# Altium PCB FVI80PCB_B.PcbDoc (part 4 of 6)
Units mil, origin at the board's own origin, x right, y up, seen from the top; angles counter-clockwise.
Board outline 3540 x 3115 mil, 12 copper layers (Top Layer, Int1(GND), Int2(Signal), Int3(GND), Int4(Signal), Int5 (GND&PW), Int6 (GND&PW), Int7(Signal), Int8(GND), Int9(Signal), Int10(GND), Bottom Layer), stack 77.136 mil thick; 488 components, 321 nets, 1809 pads, 882 vias.
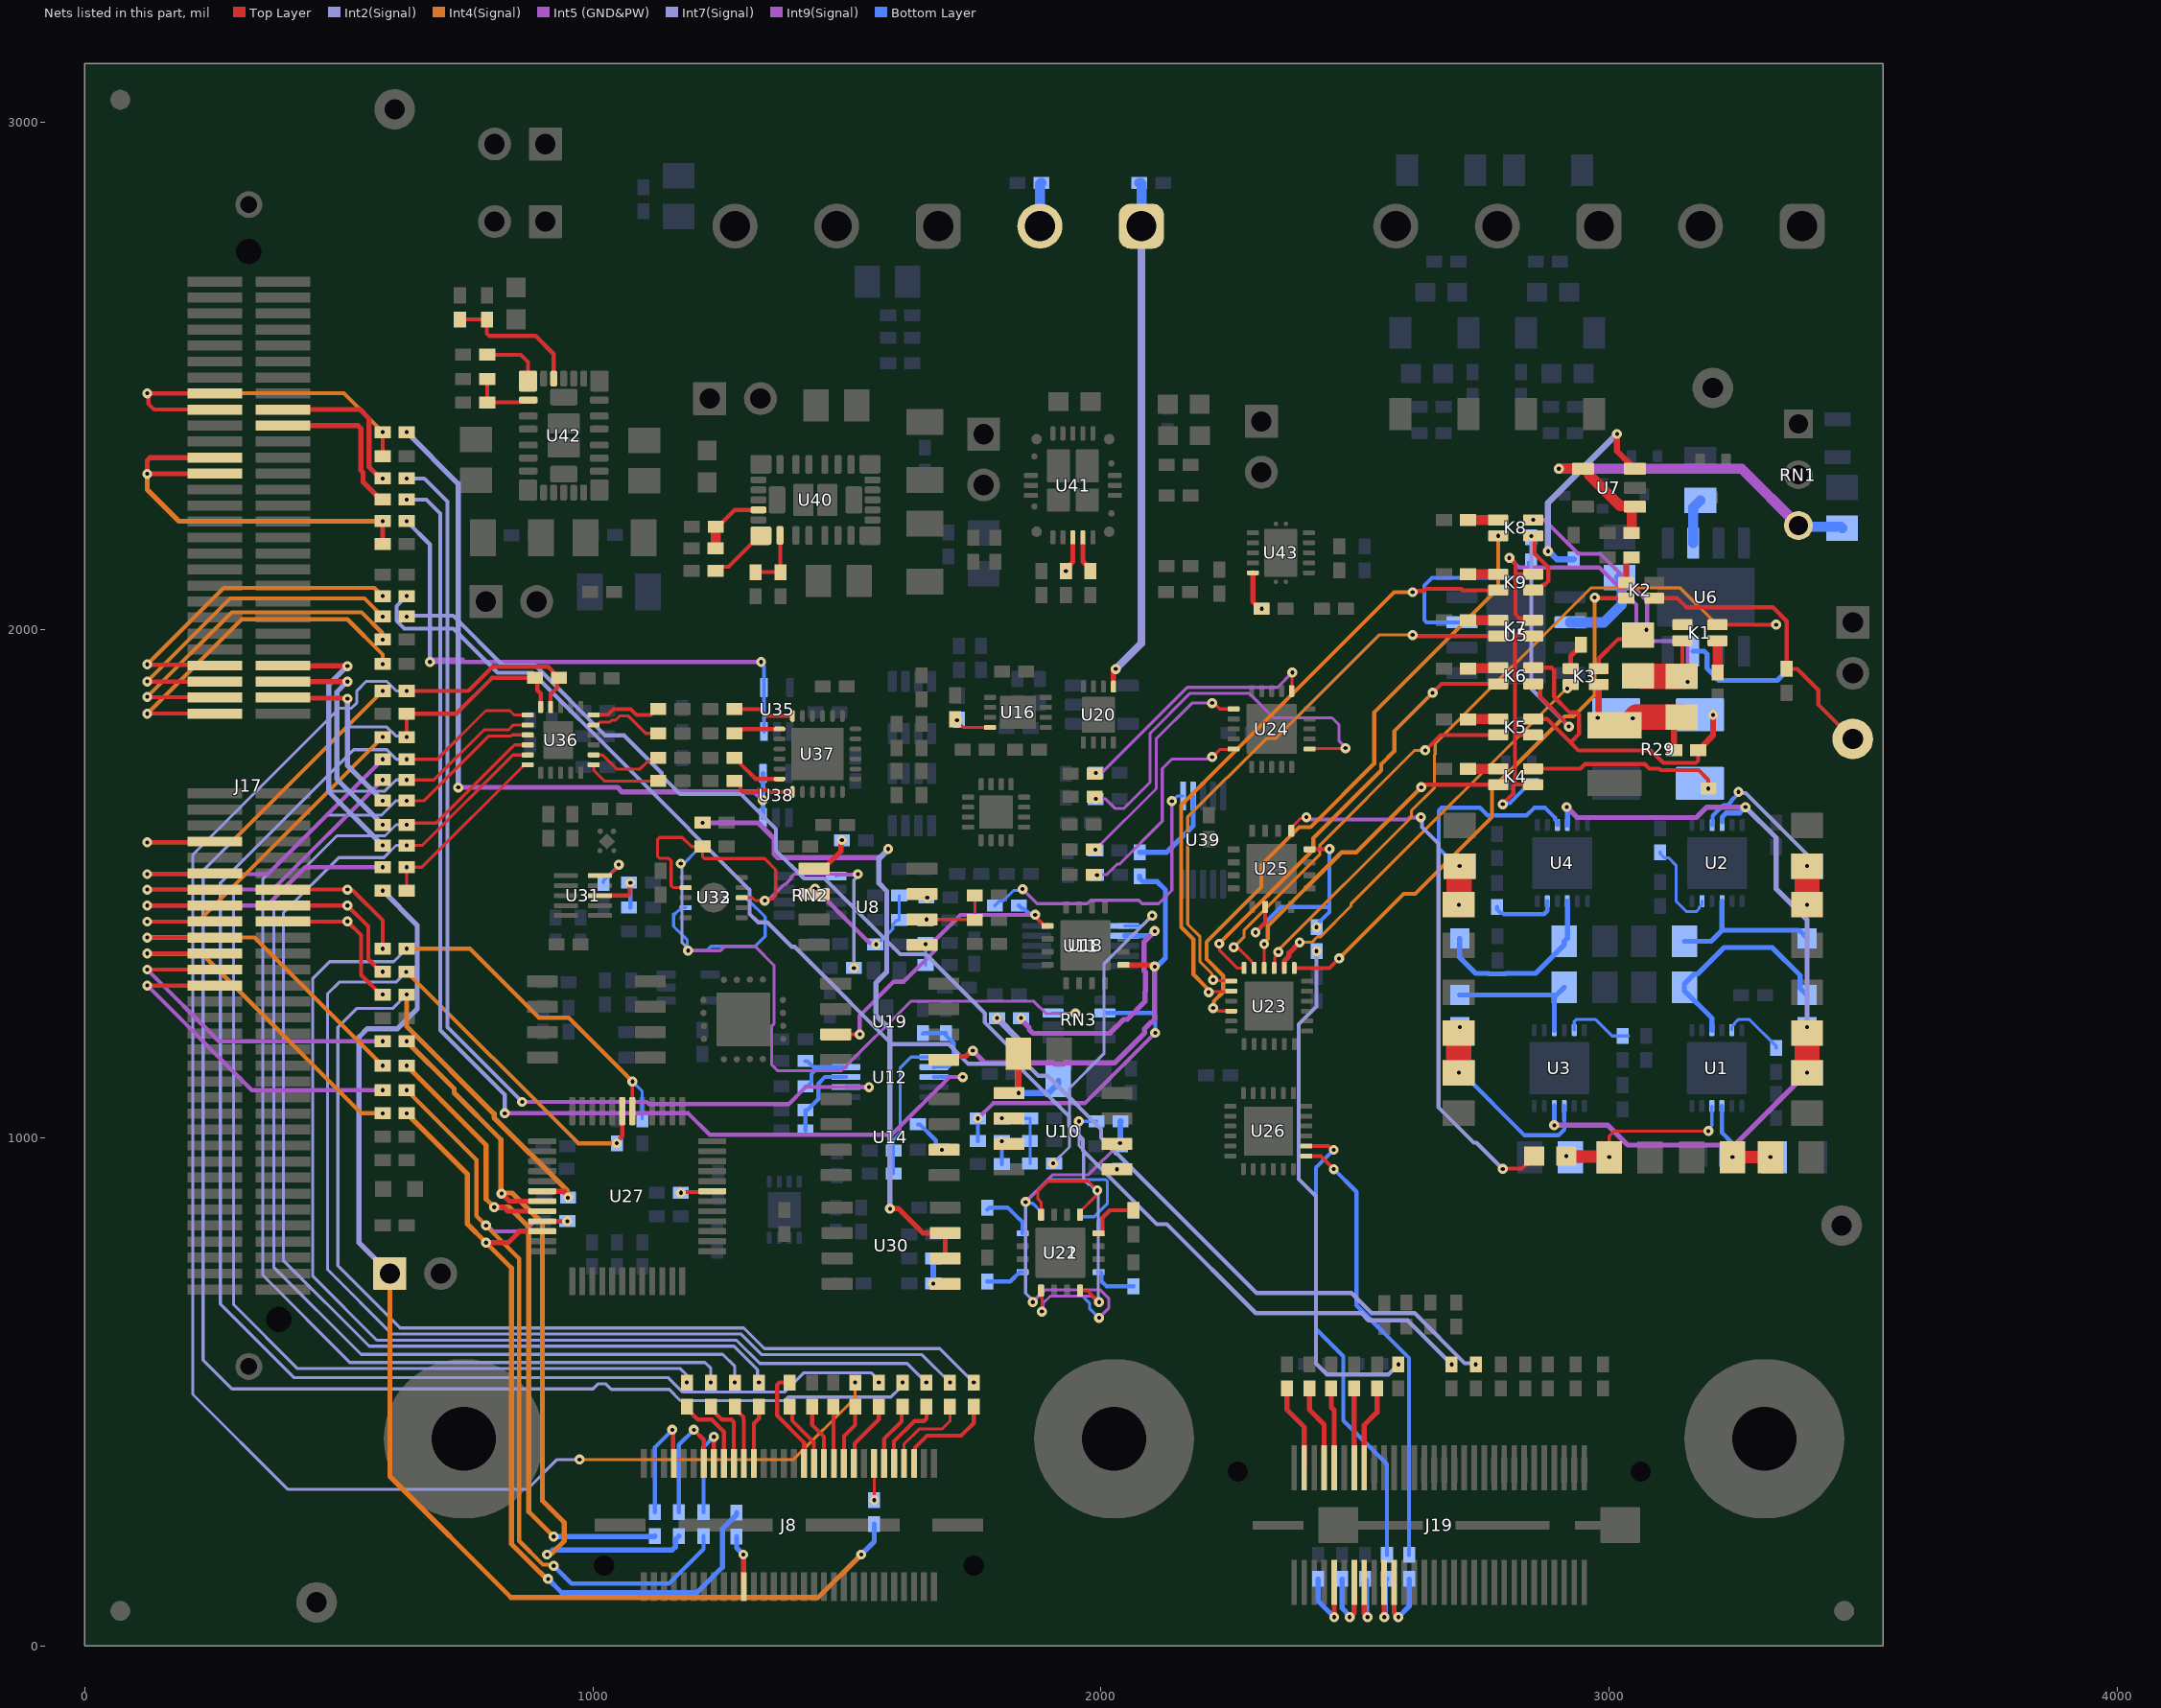
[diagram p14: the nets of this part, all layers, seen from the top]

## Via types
v1: diameter 19.68, hole 7.87, Top Layer to Bottom Layer, tented both sides, 834 vias
v2: diameter 19.68, hole 7.87, Top Layer to Bottom Layer, 39 vias
v3: diameter 23.62, hole 11.81, Top Layer to Bottom Layer, tented both sides, 5 vias
v4: diameter 19.68, hole 7.87, Top Layer to Bottom Layer, tented bottom, 4 vias

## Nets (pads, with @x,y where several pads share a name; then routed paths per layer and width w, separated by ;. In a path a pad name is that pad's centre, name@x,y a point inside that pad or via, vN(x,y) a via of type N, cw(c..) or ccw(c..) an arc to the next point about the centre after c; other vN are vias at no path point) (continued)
NetJ4_1: J4.1 R110.2 U20.1 | length 1017.6
  Top Layer w10: U20.1@2024.73,1888.53 2024.73,1915.97 2029.33,1920.57 v1(2029.33,1923.2)
  Int2(Signal) w15: v1(2029.33,1923.2) 2080,1973.86 J4.1@2080,2795
  Bottom Layer w20: R110.2@2075.75,2880 2078.19,2880 2080,2878.19 J4.1@2080,2795
NetJ4_2: J4.2 R113.1 | length 87.2
  Bottom Layer w20: J4.2@1880,2795 1880,2878.19 1881.81,2880 R113.1@1883.22,2880
NetJ8_6: J8.6 R140.2 | length 199.9
  Top Layer w8: J8.6@1632.3,359.5 1634.3,361.5 1634.3,390.44 1657.86,414 1725.04,414 1749.79,438.75 R140.2@1749.79,471.38
NetJ8_8: J8.8 R131.2 | length 175.8
  Top Layer w6: J8.8@1612.6,359.5 1612.6,397.6 1642,427 1687.1,427 1703.1,443 R131.2@1703.1,471.38
NetJ8_10: J8.10 R139.2 | length 150
  Top Layer w8: J8.10@1592.9,359.5 1592.9,402.9 1633,443 1652.33,443 1657.02,447.69 1657.02,470.78 R139.2@1656.42,471.38
NetJ8_12: J8.12 R216.2 | length 127
  Top Layer w8: J8.12@1573.2,359.5 1573.2,407.2 1608,442 1608,469.64 R216.2@1609.74,471.38
NetJ8_14: J8.14 R231.2 | length 76.7
  Top Layer w6: J8.14@1553.5,359.5 1553.75,359.25 1553.75,283.25 v1@1554,283
  other v1: 1554,287.24
NetJ8_18: J8.18 R214.2 | length 132.2
  Top Layer w8: J8.18@1514.1,359.5 1515.54,360.94 1515.54,398.54 1563.05,446.05 R214.2@1563.05,471.38
NetJ8_20: J8.20 R215.2 | length 121
  Top Layer w8: J8.20@1494.4,359.5 1494.4,413.03 1516.37,435 R215.2@1516.37,471.38
NetJ8_22: J8.22 R226.2 | length 112.6
  Top Layer w8: R226.2@1473,471.38 1473.85,470.53 1473.85,360.35 J8.22@1474.7,359.5
NetJ8_24: J8.24 R227.2 | length 118.4
  Top Layer w8: R227.2@1432,468.38 1432,435 1455,412 J8.24@1455,359.5
NetJ8_26: J8.26 R228.2 | length 131.9
  Top Layer w8: R228.2@1387,471.38 1392.85,465.53 1392.85,443.63 1435.3,401.18 J8.26@1435.3,359.5
NetJ8_28: J8.28 R228.1 | length 202.3
  Top Layer w8: R228.1@1387,518.62 1367.58,518.62 1362.9,513.94 1362.9,453.78 1415.6,401.08 J8.28@1415.6,359.5
NetJ8_38: J8.38 R222.2 | length 116
  Top Layer w8: J8.38@1317.1,359.5 1317.1,438.08 1326.96,447.94 R222.2@1326.96,471.38
NetJ8_39: J8.39 R220.1 | length 104.9
  Top Layer w10: v1(1296.35,180) 1296.88,179.48 1296.88,117.02 J8.39@1297.4,116.5
  Bottom Layer w10: R220.1@1283,215.38 1283,193.31 v1@1296.31,180
NetJ8_40: J8.40 R223.2 | length 119.2
  Top Layer w8: R223.2@1279.64,471.38 1279.64,467.44 1296.35,450.73 1296.35,446 1297.4,444.95 J8.40@1297.4,359.5
NetJ8_42: J8.42 R224.2 | length 141.7
  Top Layer w8: R224.2@1232.32,471.38 1232.32,467.44 1254.13,445.63 1273.01,445.63 1277.7,440.94 J8.42@1277.7,359.5
NetJ8_44: J8.44 R225.2 | length 158.2
  Top Layer w8: R225.2@1185,471.38 1185,467.44 1206.81,445.63 1234.33,445.63 1258,421.96 J8.44@1258,359.5
NetJ8_46: J8.46 R221.1 | length 208.9
  Top Layer w8: v1(1238.16,411.79) 1238.23,411.72 1238.23,359.57 J8.46@1238.3,359.5
  Bottom Layer w8: R221.1@1218,263.62 1218,391.63 v1(1238.16,411.79)
NetJ8_48: J8.48 R218.1 | length 248.7
  Top Layer w8: v1(1198.9,425.69) 1218.6,405.99 J8.48@1218.6,359.5
  Bottom Layer w8: R218.1@1169.34,263.62 1169.34,396.13 v1(1198.9,425.69)
NetJ8_54: J8.54 R219.1 | length 243.6
  Top Layer w8: v1(1156.46,425.69) 1157.98,424.17 1157.98,361.02 J8.54@1159.5,359.5
  Bottom Layer w8: R219.1@1122.4,263.62 1122.4,391.63 v1(1156.46,425.69)
NetJ14_1: J14.1 R217.2 R231.1 | length 2420.8
  Int4(Signal) w10: J14.1@600.5,733.19 600.5,334.03 839.04,95.48 1443.79,95.48 v1(1528.31,180)
  Int7(Signal) w10: v1(586.38,1487) 654.59,1418.79 654.59,1254.22 615.53,1215.16 556.16,1215.16 540,1199 540,793.69 J14.1@600.5,733.19
  Bottom Layer w10: v1(1528.31,180) 1554,205.69 R231.1@1554,240
NetJ17_15: J17.15 J17.17 R163.1 R164.2 | length 833
  Top Layer w8: v1(123,2466.03) v1@123.28,2465.75 ; J17.17@256.07,2433.98 136.56,2433.98 125.24,2445.3 125.24,2463.79 v1@123.28,2465.75 ; J17.15@256.07,2465.47 255.79,2465.75 v1@123.28,2465.75 ; R164.2@586.38,2341.65 v1(586.38,2389.56)
  Int4(Signal) w8: v1(123,2466.03) 509.9,2466.03 v1(586.38,2389.56)
NetJ17_18: J17.18 R165.1 | length 308.3
  Top Layer w10: J17.18@389.93,2433.98 541.96,2433.98 559.63,2416.3 559.63,2358.02 559.63,2321.18 582.44,2298.37 v1(586.38,2298.37)
NetJ17_20: J17.20 R166.1 | length 316
  Top Layer w10: J17.20@389.93,2402.48 537.77,2402.48 543.63,2396.62 543.63,2314.55 548,2310.18 548,2291.25 582.44,2256.81 R166.1@586.38,2256.81
NetJ17_23: J17.23 J17.25 R167.1 R168.2 | length 860.1
  Top Layer w10: J17.25@256.07,2307.99 255.76,2307.68 123.31,2307.68 v1(123,2307.37) 123,2333.63 128.86,2339.49 J17.23@256.07,2339.49 ; R168.2@586.38,2169.39 586.38,2214.11 v1(586.5,2214.24)
  Int4(Signal) w10: v1(123,2307.37) 123,2276.5 185.26,2214.24 v1(586.5,2214.24)
NetJ17_49: J17.49 R169.2 | length 666.5
  Top Layer w8: v1(123,1932.44) 124.2,1931.24 254.87,1931.24 J17.49@256.07,1930.04
  Int4(Signal) w8: v1(123,1932.44) 273.56,2083 570.11,2083 v1(586.38,2066.73)
NetJ17_50: J17.50 R170.1 | length 539.8
  Top Layer w10: J17.50@389.93,1930.04 390.45,1929.52 516.48,1929.52 v1(517,1929)
  Int2(Signal) w10: v1(517,1929) 480.16,1892.16 480.16,1682.22 v1(586.38,1576)
NetJ17_51: J17.51 R171.2 | length 678.9
  Top Layer w8: v1(123,1898.63) v1(123,1898.63) 256.03,1898.59 J17.51@256.07,1898.54
  Int4(Signal) w8: v1(123,1898.63) 286.37,2062 550.8,2062 v1(586.38,2026.43)
NetJ17_52: J17.52 R172.1 | length 455
  Top Layer w10: J17.52@389.93,1898.54 v1(517,1898.54)
  Int2(Signal) w10: v1(517,1898.54) 496.16,1877.7 496.16,1706.81 v1(586.38,1616.59)
NetJ17_53: J17.53 R173.2 | length 695.7
  Top Layer w8: v1(123,1868.46) 123.71,1867.75 255.37,1867.75 J17.53@256.07,1867.05
  Int4(Signal) w8: v1(123,1868.46) 289.54,2035 545,2035 585.21,1994.79 585.21,1982.24 v1(586.38,1981.07)
NetJ17_54: J17.54 R174.1 | length 357.6
  Top Layer w10: J17.54@389.93,1867.05 390.99,1865.98 515.93,1865.98 v1(517,1864.92)
  Int2(Signal) w10: v1(517,1864.92) 517,1733.39 v1(586.38,1664.02)
NetJ17_55: J17.55 R175.2 | length 720.9
  Top Layer w8: v1(123,1835.3) 123.13,1835.42 255.94,1835.42 J17.55@256.07,1835.55
  Int4(Signal) w8: v1(123,1835.3) 308.7,2021 517.09,2021 586.38,1951.72 v1(586.38,1933)
NetJ17_63: J17.63 R177.2 | length 720.5
  Top Layer w8: v1(123,1582) 123.79,1582.79 255.28,1582.79 J17.63@256.07,1583.58
  Int4(Signal) w8: v1(123,1582) 288.38,1582 v1(586.38,1880)
NetJ17_67: J17.67 R178.2 | length 690.6
  Top Layer w8: v1(123,1519.37) 123.61,1519.98 255.46,1519.98 J17.67@256.07,1520.59
  Int5 (GND&PW) w8: v1(123,1519.37) 360.31,1519.37 v1(586.38,1745.44)
NetJ17_69: J17.69 R179.2 | length 685.9
  Top Layer w8: v1(123,1489.1) J17.69@256.07,1489.1
  Int5 (GND&PW) w8: v1(123,1489.1) 370.47,1489.1 v1(586.38,1705)
NetJ17_70: J17.70 R180.2 | length 277.6
  Top Layer w8: J17.70@389.93,1489.1 v1(517,1489.1) 519.24,1486.86 528.14,1486.86 586.5,1428.5 v1(586.5,1372.55)
NetJ17_71: J17.71 R181.2 | length 627.7
  Top Layer w8: v1(123,1457.6) J17.71@256.07,1457.6
  Int5 (GND&PW) w8: v1(123,1457.6) 358.78,1457.6 434.18,1533 v1(586.38,1533)
NetJ17_72: J17.72 R182.2 | length 288.6
  Top Layer w8: J17.72@389.93,1457.6 v1(517,1457.6) 558,1416.6 558,1351.75 582.56,1327.19 v1(586.5,1327.19)
NetJ17_73: J17.73 R183.2 | length 746.9
  Top Layer w8: v1@117.16,1426.01 v1@117.2,1426.06 ; v1@123.05,1426.06 256.03,1426.06 J17.73@256.07,1426.1
  Int4(Signal) w8: v1(123,1426.01) 223.14,1426.01 v1(586.38,1789.25)
NetJ17_74: J17.74 R184.2 | length 302.2
  Top Layer w8: J17.74@389.93,1426.1 390.03,1426.21 516.9,1426.21 v1(517,1426.31) 544,1399.31 544,1345.95 544.2,1345.75 544.2,1320.77 582.56,1282.41 v1(586.5,1282.41)
NetJ17_75: J17.75 R185.2 | length 701
  Top Layer w8: v1(123,1394.61) J17.75@256.07,1394.61
  Int4(Signal) w8: v1(123,1394.61) 334.05,1394.61 v1(586.38,1142.28)
NetJ17_77: J17.77 R186.2 | length 726.8
  Top Layer w8: v1(123,1363.11) J17.77@256.07,1363.11
  Int4(Signal) w8: v1(123,1363.11) 230.1,1363.11 544.5,1048.71 v1(586.5,1048.71)
NetJ17_79: J17.79 R187.2 | length 655.1
  Top Layer w8: v1(123,1331.62) J17.79@256.07,1331.62
  Int5 (GND&PW) w8: v1(123,1331.62) 264.28,1190.34 v1(586.5,1190.34)
NetJ17_81: J17.81 R188.2 | length 681.9
  Top Layer w8: v1(123,1300.12) J17.81@256.07,1300.12
  Int5 (GND&PW) w8: v1(123,1300.12) 329.06,1094.06 v1(586.5,1094.06)
NetJ19_4: J19.4 R209.2 | length 170.3
  Top Layer w10: R209.2@2366.34,507.1 2366.34,465 2400.25,431.09 J19.4@2400.25,350.8
NetJ19_8: J19.8 R207.2 | length 168.3
  Top Layer w10: R207.2@2410.59,507.1 2410.59,465 2439.62,435.97 J19.8@2439.62,350.8
NetJ19_9: J19.9 R206.1 | length 158.9
  Top Layer w10: J19.9@2459.31,125.21 v1(2459.31,56.87) 2459.31,55.69 v1@2460,55
  Bottom Layer w10: R206.1@2427.38,132.02 2427.38,88.79 v1(2459.31,56.87)
NetJ19_10: J19.10 R205.2 | length 158.7
  Top Layer w10: R205.2@2453.46,507.1 2453.46,470 2459.31,464.16 J19.10@2459.31,350.8
NetJ19_13: J19.13 R203.1 | length 154.5
  Top Layer w10: v1@2489.73,55.69 v1(2489.73,56.87) 2489.73,57.08 2498.68,66.03 J19.13@2498.68,125.21
  Bottom Layer w10: R203.1@2475,132.02 2475,74.22 2489.73,59.49 v1(2489.73,56.87)
NetJ19_14: J19.14 R202.2 | length 156.5
  Top Layer w10: R202.2@2498.15,507.1 2498.41,506.83 2498.41,351.06 J19.14@2498.68,350.8
NetJ19_15: J19.15 R201.1 | length 150.2
  Top Layer w10: J19.15@2518.36,125.21 2518.36,64.26 2525,57.62 v1(2525,56.87) v1@2525,55
  Bottom Layer w10: R201.1@2520,132.02 2523.15,128.88 2523.15,58.72 v1(2525,56.87)
NetJ19_16: J19.16 R200.2 | length 166.7
  Top Layer w10: J19.16@2518.36,350.8 2518.36,434.84 2543.52,460 R200.2@2543.52,507.1
NetJ19_19: J19.19 R199.1 | length 146.8
  Top Layer w10: v1@2557.73,55.69 J19.19@2557.73,125.21
  Bottom Layer w10: v1(2557.89,56.87) 2559.74,58.72 2559.74,128.65 R199.1@2563.11,132.02
NetJ19_21: J19.21 R197.1 | length 155.6
  Top Layer w10: J19.21@2577.42,125.21 2577.42,65.07 v1(2585.62,56.87)
  Bottom Layer w10: v1(2585.62,56.87) 2606.76,78.02 R197.1@2606.76,132.02
NetK1_1: K1.1 R22.2 | length 62.5
  Top Layer w20: R22.2@3213.64,1916.36 K1.1@3213.64,1978.9
NetK1_2: K1.2 U23.3 | length 1516.6
  Top Layer w6: U23.3@2341.12,1334.57 2342.08,1335.52 2342.08,1355.38 2349.39,1362.69 v1(2349.39,1366.39)
  Top Layer w8: K1.2@3213.64,2010.4 v1(3329,2010.36) v1(3329,2010.36)
  Int4(Signal) w6: v1(2349.39,1366.39) 2349.39,1369.82 2611.16,1631.59 2611.16,1644.25 2656.67,1689.77 2656.67,1754.56 2658.1,1755.99 2658.1,1776.75 2964.2,2082.84 3140.45,2082.84 3212.93,2010.36 v1(3329,2010.36)
NetK1_3: K1.3 K2.3 K3.4 K8.4 R26.2 R31.1 TP1.1 | length 1041.7
  Top Layer w8: K3.4@2979.89,1924.23 2979.89,1943.7 3018,1981.81 3048.92,1981.81 R26.2@3057.29,1990.18 ; K2.3@3100,2057 3100,2057.76 3104.92,2062.67 3134.17,2062.67 3151.98,2044.86 3322.56,2044.86 3350,2017.42 R31.1@3350,1923.62 3370.74,1923.62 3412.02,1882.35 3412.02,1853.48 TP1.1@3480,1785.5 ; K1.3@3144.74,2010.4 K1.3@3153.6,2010.4
  Int9(Signal) w8: v1(2850.89,2216.81) 2872.75,2216.81 2939.56,2150 2983,2150 3075,2058 3075,2002 v1@3074,2001
  other v1: 3074,2000.5
NetK1_4: K1.4 K7.4 K9.4 R25.2 R26.1 | length 876.9
  Top Layer w8: v1@2804,2140 2807.55,2140 2816.08,2131.47 2816.08,2030.92 2823.97,2023.03 2847.47,2023.03 K7.4@2850.89,2019.61 ; 2818,2110 2850.81,2110 K9.4@2850.89,2109.92 ; R25.2@3142.98,1908.48 3144.74,1910.25 K1.4@3144.74,1978.9
  Top Layer w50: R26.1@3057.29,1910.18 3063.79,1910.18 3065.48,1908.48 R25.2@3142.98,1908.48
  Int9(Signal) w8: v1(2804,2142) 2823,2123 2981,2123 3054.16,2049.84 3054.16,1992.28 3068.44,1978 3149.31,1978 3155,1972.31 v1(3155,1898) v1@3154,1897
NetK2_1: K2.1 R23.2 | length 55.5
  Top Layer w12: K2.1@3034.11,2094.17 3034.11,2136.43 3040.68,2143 R23.2@3044.62,2143
NetK2_2: K2.2 U23.1 | length 1101.2
  Top Layer w8: U23.1@2380.49,1334.57 2449.76,1334.57 v1(2468.79,1353.6) ; v1(2972,2064) 2973.33,2062.67 K2.2@3034.11,2062.67
  Int4(Signal) w8: v1(2468.79,1353.6) 2596,1480.81 2618.87,1480.81 2770.08,1632.02 2770.08,1686.95 2912.94,1829.81 2930.2,1829.81 2972,1871.61 v1(2972,2064)
NetK3_1: K3.1 R30.2 | length 56.9
  Top Layer w10: K3.1@2924.77,1924.23 2924.77,1948.77 2936.63,1960.63 2938.19,1960.63 2947,1969.44 R30.2@2947,1971
NetK3_2: K3.2 U23.2 | length 799.3
  Top Layer w10: U23.2@2360.81,1334.57 2361.08,1334.84 2361.08,1348.61 2370.23,1357.76 2370.23,1363.96 2391.3,1385.04 v1(2391.3,1385.09)
  Int4(Signal) w6: v1(2391.3,1385.09) 2415.1,1385.09 2426.3,1396.29 2432.35,1396.29 2492.16,1456.1 2492.16,1460.16 2917,1885 v1(2918,1885)
NetK3_3: K3.3 R24.2 R25.1 R28.2 R29.I1 | length 276.4
  Top Layer w12: v1(2978,1827) 2979.89,1828.89 K3.3@2979.89,1892.74 ; R28.2@3128.36,1763.04 3128.36,1813.86 R25.1@3142.98,1828.48
  Top Layer w50: R24.2@3011.2,1812.6 3038.76,1812.6 3054.65,1828.48 R25.1@3142.98,1828.48
  other v1: 3047,1826
NetK4_1: K4.1 R33.2 | length 59.8
  Top Layer w8: R33.2@2723,1725 2724.97,1726.97 R33.2@2734.75,1726.97
  Top Layer w20: R33.2@2734.75,1726.97 K4.1@2781.99,1726.97
NetK4_2: K4.2 U23.4 | length 655.1
  Top Layer w6: U23.4@2321.44,1334.57 v1(2321.44,1381.72)
  Top Layer w8: v1@2630,1689.74 v1(2630.61,1690.36) 2635.74,1695.48 K4.2@2781.99,1695.48
  Int4(Signal) w8: v1(2321.44,1381.72) 2321.44,1384.88 2328.69,1392.14 2328.69,1417.22 2473.92,1562.45 2502.7,1562.45 v1(2630.61,1690.36)
NetK4_3: K4.3 K5.3 K7.3 R41.2 | length 518.2
  Top Layer w8: v1(2791,1657) 2811.68,1677.68 2811.68,1692.68 2815,1696 ; K4.3@2848,1695 2847,1696 2815,1696 ; K5.3@2850.89,1793.31 2815,1793.31 ; K7.3@2850.89,1988.11 2848.5,1990.5 2819.69,1990.5 2815,1985.81 2815,1793.31 ; 2815,1696 2815,1793.31
  Bottom Layer w8: v1(2791,1657) 2793.24,1659.24 2805.01,1659.24 2839.77,1694 R41.2@2847,1694
NetK4_4: K4.4 R27.1 R29.E2 | length 378.5
  Top Layer w8: K4.4@2850.89,1726.97 2944.04,1726.97 2953.08,1736.01 3070.58,1736.01 3079.62,1726.97 3098.82,1726.97 3101.54,1724.25 3176.47,1724.25 3195.77,1704.96 v1(3195.77,1687.99)
NetK5_1: K5.1 R34.2 | length 59.5
  Top Layer w20: R34.2@2722.76,1824.08 2723.12,1824.45 2781.63,1824.45 K5.1@2781.99,1824.81
NetK5_2: K5.2 U23.5 | length 774.5
  Top Layer w6: v1(2261.38,1375.38) 2264,1372.76 2271.98,1372.76 2295.79,1348.94 2295.79,1347.61 2301.75,1341.65 U23.5@2301.75,1334.57
  Top Layer w8: v1(2638.5,1763.04) 2668.78,1793.31 K5.2@2781.99,1793.31
  Int4(Signal) w6: v1(2261.38,1375.38) 2282.07,1396.06 2282.07,1409.41 2431.16,1558.5 2431.16,1576.8 2617.4,1763.04 v1(2638.5,1763.04)
NetK5_4: K5.4 K6.4 R28.1 R29.E1 | length 684.4
  Top Layer w8: K5.4@2850.89,1824.81 2878.25,1824.81 2924.53,1778.53 2940.02,1763.04 3082.55,1763.04 3107.34,1738.25 3170.91,1738.25 3175.6,1742.94 R28.1@3175.6,1763.04 ; K6.4@2850.89,1925.57 2887.31,1925.57 2892,1920.88 2892,1868.27 2922.11,1838.16 2936.31,1838.16 2941,1833.47 2941,1795 2927,1781
  Top Layer w12: R28.1@3175.6,1763.04 3179.54,1763.04 3185.35,1768.85 3185.35,1772.79 3205,1792.44 v1(3205,1833.03)
NetK6_1: K6.1 R35.2 | length 59.8
  Top Layer w20: R35.2@2722.76,1924.23 2723.43,1924.9 2781.32,1924.9 K6.1@2781.99,1925.57
NetK6_2: K6.2 U23.6 | length 880.7
  Top Layer w6: v1(2233.01,1382.6) 2233.81,1381.8 2233.81,1368.75 2267.99,1334.57 U23.6@2282.07,1334.57
  Top Layer w8: v1(2653.01,1876.38) 2670.71,1894.07 K6.2@2781.99,1894.07
  Int4(Signal) w8: v1(2233.01,1382.6) 2418.16,1567.75 2418.16,1590.16 2551.89,1723.89 2551.89,1735.89 2577.57,1761.57 2577.57,1800.94 v1(2653.01,1876.38)
NetK6_3: K6.3 K8.3 K9.3 R40.1 | length 660.9
  Top Layer w8: K6.3@2850.89,1894.07 2857.8,1894.07 2864.62,1887.24 2864.62,1868.38 2921.16,1811.84 v1(2921.16,1809.97) ; K9.3@2850.89,2078.42 2859.75,2078.42 2870.42,2089.09 2873.57,2089.09 2880.57,2096.09 2880.57,2124 2854,2150.57 K8.3@2854,2185
  Int2(Signal) w8: v1@2847,2186 v1(2847,2185) 2847,1884.12 v1(2921.16,1809.97)
NetK7_1: K7.1 R36.2 | length 59.2
  Top Layer w20: R36.2@2722.76,2019.61 K7.1@2781.99,2019.61
NetK7_2: K7.2 U23.7 | length 1138.3
  Top Layer w6: v1(2221,1311.13) 2222.08,1310.05 2255.4,1310.05 U23.7@2256.48,1308.98
  Top Layer w8: v1(2613.5,1990.18) 2615.57,1988.11 K7.2@2781.99,1988.11
  Int4(Signal) w6: v1(2221,1311.13) 2218.51,1313.61 2218.51,1323.29 2195.13,1346.67 2195.13,1396.27 2171,1420.41 2171,1631.95 2325.39,1786.34 2343.99,1786.34 2445.79,1888.14 2445.79,1888.38 2547.59,1990.18 v1(2613.5,1990.18)
NetK8_1: K8.1 R38.2 | length 59.2
  Top Layer w20: R38.2@2722.76,2216.81 K8.1@2781.99,2216.81
NetK8_2: K8.2 U23.10 | length 1240.1
  Top Layer w6: v1(2221,1255.83) 2224.7,1255.83 2230.61,1249.92 U23.10@2256.48,1249.92
  Int4(Signal) w8: v1(2221,1255.83) 2222.47,1257.3 2222.47,1269.25 2240.84,1287.62 2240.84,1319.35 2208.13,1352.06 2208.13,1386.07 2315.89,1493.82 2315.89,1537.57 2390.15,1611.84 2412.73,1611.84 2537.89,1737 2537.89,1837.81 2781.99,2081.91 v1(2781.99,2185.31)
NetK9_1: K9.1 R37.2 | length 59.2
  Top Layer w20: R37.2@2722.76,2109.92 K9.1@2781.99,2109.92
NetK9_2: K9.2 U23.8 | length 1237.2
  Top Layer w6: v1(2212.13,1286.97) 2213.29,1288.13 2255.31,1288.13 U23.8@2256.48,1289.29
  Top Layer w8: v1(2613.5,2074.47) 2615.74,2076.71 2635.21,2076.71 2639.34,2080.84 2709.25,2080.84 2711.67,2078.42 K9.2@2781.99,2078.42
  Int4(Signal) w8: v1(2212.13,1286.97) 2212.13,1290.13 2207.17,1295.08 2207.17,1296.9 2182.13,1321.94 2182.13,1390.89 2158,1415.02 2158,1655.06 2577.41,2074.47 v1(2613.5,2074.47)
NetR1_1: R1.1 R7.1 U1.9 | length 437.6
  Bottom Layer w10: U1.9@3202.63,1212.42 3202.63,1236.15 3148.52,1290.25 R1.1@3148.52,1296.75 3148.52,1303.25 3168.52,1323.25 3175.02,1323.25 3226.62,1374.84 3321.38,1374.84 3376.3,1319.92 3376.3,1295.12 R7.1@3390,1281.42
NetR2_1: R2.1 R11.2 U2.9 | length 315.1
  Bottom Layer w10: R2.1@3148.52,1387.25 3200.96,1387.25 3222.71,1409 ; U2.9@3222.71,1466.37 3222.71,1409 ; R11.2@3390,1392.97 3390,1393.95 3376.3,1407.65 3375.31,1407.65 3373.97,1409 3222.71,1409
NetR3_1: R3.1 U25.1 | length 1107.9
  Top Layer w6: U25.1@2374.57,1604.61 2374.57,1610.52 2393.12,1629.06 2401.89,1629.06 v1(2404.51,1631.68)
  Top Layer w8: v1@2792,940 2828.54,940 2837.19,948.66 2837.19,949.64 2851.89,964.34 R3.1@2852.88,964.34
  Int2(Signal) w8: v1(2630,1631.68) 2632.24,1629.44 2632.24,1612.11 2664.42,1579.92 2664.42,1060.46 2734.11,990.77 2739.23,990.77 v1(2791,939)
  Int9(Signal) w8: v1(2404.51,1631.68) 2407.67,1631.68 2412.35,1627 2604.16,1627 2608.16,1631 2629.32,1631 v1(2630,1631.68)
NetR3_2: R3.2 R4.2 R5.2 R6.2 U1.4 | length 378.2
  Top Layer w6: v1(3000.72,962.37) 3000.72,968.87 3000.72,1003.71 3010.57,1013.55 v1(3195.77,1013.55)
  Top Layer w25: v1(2915.87,964.34) 2916.85,963.36 2999.74,963.36 v1(3000.72,962.37)
  Bottom Layer w6: v1(3195.77,1013.55) 3195.77,1017.26 3202.63,1024.12 U1.4@3202.63,1062.82
NetR7_2: R7.2 R12.2 R13.2 R14.2 U2.4 U3.4 U4.4 | length 1640
  Top Layer w50: v1(3390,1128.52) R12.2@3390,1206.97
  Int2(Signal) w10: v1(3268.57,1651.36) 3329.29,1590.65 3329.29,1490.4 3390,1429.69 v1(3390,1218.43)
  Int9(Signal) w10: v1(2892.41,1025.08) 2998.16,1025.08 3037.24,986 3247.48,986 v1(3390,1128.52) ; v1(2917,1651.57) 2937.84,1630.73 3172.09,1630.73 3192.73,1651.36 v1(3268.57,1651.36)
  Bottom Layer w10: v1(2892.41,1025.08) U3.4@2892.41,1062.82 ; v1(2917,1651.57) 2918.23,1650.34 U4.4@2918.23,1615.97 ; U2.4@3222.79,1622.78 3222.79,1631.76 3231.03,1640 3257.21,1640 v1(3268.57,1651.36)
NetR8_1: R8.1 R15.2 R16.2 R17.2 U1.3 | length 258.1
  Top Layer w25: v1(3243.34,962.37) v1(3317.81,962.37)
  Bottom Layer w8: U1.3@3222.32,1062.82 3222.32,1010.33 3243.34,989.31 v1(3243.34,962.37)
  Bottom Layer w25: v1(3243.34,962.37) v1(3317.81,962.37)
NetR9_1: R9.1 U1.11 | length 126.3
  Bottom Layer w6: U1.11@3242,1212.42 3242,1219.31 3247.76,1225.08 3247.76,1226.81 3254.19,1233.24 3276.7,1233.24 3329,1180.94 R9.1@3329,1177
NetR10_1: R10.1 U2.11 | length 187.6
  Bottom Layer w6: R10.1@3100.81,1562.35 3100.81,1560.11 3109.62,1551.3 3118.04,1551.3 3132.16,1537.18 3132.16,1466.53 3153.13,1445.55 3171.63,1445.55 3177.57,1451.5 3177.57,1453.71 3183.34,1459.48 U2.11@3183.34,1466.37
NetR11_1: R11.1 R72.2 R73.2 R74.2 U2.3 | length 376.5
  Top Layer w50: v1(3390,1459.16) v1(3390,1535.25)
  Int2(Signal) w8: v1(3255,1681.17) 3257.24,1678.93 3269.07,1678.93 3390,1558 v1(3390,1535.25)
  Bottom Layer w8: U2.3@3203.02,1615.97 3203.95,1616.89 3203.95,1634.13 3225.32,1655.51 3233.73,1655.51 3241.45,1663.23 3241.45,1664.46 3255,1678.01 v1(3255,1681.17)
NetR18_1: R18.1 R83.2 U3.9 | length 283
  Bottom Layer w10: R83.2@2706.33,1281.42 R18.1@2896.81,1281.42 ; U3.9@2892.41,1212.42 2892.41,1277.02 R18.1@2896.81,1281.42 ; R18.1@2912.15,1296.75 R18.1@2896.81,1281.42
NetR19_1: R19.1 R84.2 U4.9 | length 369
  Bottom Layer w10: R84.2@2706.33,1392.97 2706.33,1355.35 2737.62,1324.07 2762.82,1324.07 2763.97,1322.91 2796.71,1322.91 2797.86,1324.07 2855.46,1324.07 2912.15,1380.75 R19.1@2912.15,1387.25 2918.23,1393.33 U4.9@2918.23,1466.37
NetR20_1: R20.1 U3.11 | length 139.3
  Bottom Layer w6: U3.11@2931.78,1212.42 2931.78,1229.72 2935.3,1233.24 2973.96,1233.24 3006.2,1201 3039,1201
NetR21_1: R21.1 U4.11 | length 129.2
  Bottom Layer w8: R21.1@2779.54,1454.64 2779.54,1450.7 2787.35,1442.89 2791.29,1442.89 2793.48,1440.71 2872.33,1440.71 2878.86,1447.23 U4.11@2878.86,1466.37
NetR39_1: R39.1 U5.6 | length 170.9
  Bottom Layer w20: U5.6@2923.35,2015 2990.12,2015 3025,2049.88 3025,2099 R39.1@3021,2103
NetR40_2: R40.2 U5.3 | length 381.7
  Bottom Layer w8: U5.3@2710.75,2015 2641.19,2015 2636.5,2019.69 2636.5,2087.5 2652,2103 2834,2103 2843,2112 R40.2@2843,2133
NetR42_1: R42.1 R47.1 RN1.3 U7.1 U7.4 | length 844.7
  Top Layer w20: v1(2901.47,2317.4) U7.4@2948.82,2317.4 2958.66,2317.4 2960.47,2315.59 2960.47,2305.75 3021.81,2244.41 3049.37,2244.41 U7.1@3051.18,2242.6 ; R47.1@3044.62,2191 3044.62,2240.79 U7.1@3046.43,2242.6
  Int9(Signal) w20: v1(2901.47,2317.4) 3261.2,2317.4 RN1.3@3373,2205.6
  Bottom Layer w20: RN1.3@3373,2205.6 3375.5,2203.1 3456.5,2203.1 R42.1@3459,2200.6
NetR44_2: R44.2 U6.6 | length 89.8
  Bottom Layer w20: U6.6@3166,2171 3166,2241 R44.2@3180,2255
NetR45_1: R45.1 U6.3 | length 236.1
  Bottom Layer w10: U6.3@3166,1958.4 3187.33,1958.4 3193.19,1952.54 3193.19,1924.3 3216.6,1900.89 3331.2,1900.89 3350,1919.69 R45.1@3350,1923.62
NetR46_1: R46.1 U7.3 | length 428
  Top Layer w12: v1(3016,2386) 3016,2352.58 U7.3@3051.18,2317.4
  Int2(Signal) w12: v1(2880,2155) 2880,2250 v1(3016,2386)
  Bottom Layer w12: v1(2880,2155) 2882.08,2155 2897.7,2139.38 R46.1@2931,2139.38
NetR48_2: R48.2 R50.2 U8.5 | length 43.9
  Bottom Layer w6: R48.2@1655.05,1340.29 R50.2@1655.05,1384.22
  other v1: 1655.05,1381.72
NetR49_1: R49.1 U8.7
  other v1: 1658.35,1473.26
NetR52_1: R52.1 R56.1 U24.6 | length 505.9
  Top Layer w6: U24.6@2375.56,1879.99 2376.25,1880.68 2376.25,1915.66 v1(2376.95,1916.36)
  Int9(Signal) w6: v1(1989.84,1718.7) 1991.24,1720.09 2003.09,1720.09 2170.22,1887.22 2347.81,1887.22 v1(2376.95,1916.36)
NetR53_1: R53.1 R55.2 R57.2 U8.6 | length 152.5
  Top Layer w6: U8.6@1648.18,1430.19 1750.99,1430.19 R53.1@1752.09,1429.1 R57.2@1752.09,1477.19
  other v1: 1657.02,1430.19
NetR58_1: R58.1 R59.1 U24.1 | length 784.7
  Top Layer w6: U24.1@2410.99,1765.81 2411.8,1766.63 2480.65,1766.63 v1(2481.46,1767.44)
  Int9(Signal) w6: v1(1989.84,1667.34) 2009.8,1667.34 2028.64,1648.5 2044.89,1648.5 2097,1700.61 2097,1797 2175,1875 2292.35,1875 2340.19,1827.16 2454.67,1827.16 2468.84,1812.99 2468.84,1781.47 2481.46,1768.86 v1(2481.46,1767.44)
NetR60_1: R60.1 R61.2 U14.6 | length 74.2
  Bottom Layer w8: R61.2@1639.97,1026.72 1643.91,1026.72 1675.47,995.16 1675.47,984.53 1683.28,976.72 v1(1687.22,976.72)
NetR62_1: R62.1 R129.2 RN2.1 U33.3 U33.7 | length 982.6
  Top Layer w6: U33.7@1182.81,1492.94 1157.75,1492.94 1154.24,1496.46 1154.24,1545.4 1148.96,1550.67 1131.11,1550.67 1127.6,1554.19 1127.6,1587.82 1131.47,1591.69 1176.28,1591.69 1194.43,1573.54 R129.2@1216.19,1573.54 1216.19,1553.58 1219.71,1550.06 1338.02,1550.06 1360.13,1527.96 1360.13,1476.83 1353.34,1470.04 1336.02,1470.04 v1@1335.73,1470.34 ; U33.3@1293.04,1473.26 1313.85,1473.26 1319.69,1467.42 1332.32,1467.42 1335.24,1470.34 v1@1335.73,1470.34 ; v1(1338.64,1467.42) v1@1335.73,1470.34
  Int2(Signal) w6: v1(1514.04,1334.57) 1514.04,1507.86 1521.85,1515.66 v1(1521.85,1519.37)
  Int9(Signal) w6: v1(1338.64,1467.42) 1342.35,1467.42 1346.73,1471.81 1348.9,1471.81 1376.51,1499.42 1379.04,1499.42 1390.08,1510.46 1390.08,1512.99 1396.46,1519.37 v1(1521.85,1519.37)
  Bottom Layer w6: RN2.1@1479.01,1515.58 1480.91,1517.47 1519.95,1517.47 v1(1521.85,1519.37)
NetR63_1: R63.1 U8.1 | length 89.9
  Top Layer w10: U8.1@1435.58,1530.19 1454.28,1530.19 1488.56,1564.48 1488.56,1584.55 v1(1490.42,1586.4)
NetR64_1: R64.1 R65.1 R66.1 U8.2 | length 286.1
  Int9(Signal) w8: v1(1437.52,1490.85) 1545.11,1383.27 1555.55,1383.27 v1(1557.79,1381.03)
  Bottom Layer w6: R65.1@1555.82,1381.03 v1(1557.79,1381.03) 1559.76,1381.03 1590.32,1411.59 1590.32,1420.28 1599.13,1429.1 R64.1@1603.06,1429.1 R66.1@1603.06,1477.19
NetR67_1: R67.1 R69.1 U12.4 | length 136
  Bottom Layer w8: R69.1@1418.4,1101.5 1422.34,1101.5 1430.15,1109.31 1430.15,1125.84 1443.99,1139.69 ; R67.1@1418.4,1151.5 1422.34,1151.5 1434.15,1139.69 1443.99,1139.69 ; U12.4@1498.39,1139.69 1443.99,1139.69
NetR68_1: R68.1 R70.1 U12.6 | length 288.8
  Bottom Layer w6: R70.1@1592.06,930.01 R68.1@1592.06,975.49 1592.06,997.14 1604.81,1009.89 1604.81,1137.84 1626.34,1159.37 U12.6@1671.61,1159.37
NetR71_1: R71.1 R80.1 R82.1 U10.1 | length 355.1
  Top Layer w12: U10.1@1819.18,1088.36 U10.1@1832.15,1088.36 ; v1(1837.96,1088.36) U10.1@1832.15,1088.36 ; R82.1@1837.96,1166.09 1837.96,1094.17 U10.1@1832.15,1088.36
  Int2(Signal) w12: v1(1795.65,1236.21) 1837.96,1193.89 v1(1837.96,1088.36)
  Bottom Layer w12: v1(1837.96,1088.36) 1897.48,1088.36 1916.48,1107.36 R80.1@1916.48,1111.78
NetR71_2: R71.2 U11.2 | length 498
  Int9(Signal) w10: v1(1842.89,1236.21) 1842.89,1233.59 1858.89,1217.59 1858.89,1213.9 1866.79,1206 2017.68,1206 2045.23,1233.55 2051.88,1233.55 2086.78,1268.44 2086.78,1288.3 2087.84,1289.37 2087.84,1326.11 2085.16,1328.79 2085.16,1386.4 v1(2106,1407.24)
  Bottom Layer w10: U11.2@2046.81,1397.89 2094.03,1397.89 2103.38,1407.24 v1(2106,1407.24)
NetR75_1: R75.1 R77.1 U12.3 | length 164.6
  Bottom Layer w8: R77.1@1418.4,1015 R75.1@1418.4,1055 1422.34,1055 1444.15,1076.81 1444.15,1107.1 1457.05,1120 U12.3@1498.39,1120
NetR76_1: R76.1 R78.1 U12.7 | length 146.8
  Bottom Layer w8: R78.1@1650,1205 1651.38,1206.38 R76.1@1695,1206.38 ; U12.7@1671.61,1139.69 1673.52,1141.59 1701.28,1141.59 1710.16,1150.46 1710.16,1187.28 R76.1@1695,1202.44
NetR79_2: R79.2 R81.2 U10.3 | length 44.8
  Bottom Layer w8: R79.2@1805.14,948.83 v1(1805.14,993.67)
NetR81_1: R81.1 R87.1 RN3.2 | length 599.6
  Int9(Signal) w8: v1(1757.89,1038.36) 1788.05,1068.51 1968.63,1068.51 v1(2107.06,1206.95)
  Bottom Layer w8: R81.1@1757.89,993.67 v1(1757.89,1038.36) R87.1@1757.89,1038.95 ; RN3.2@2008.19,1246.17 2102.38,1246.17 2107.06,1241.48 v1(2107.06,1206.95)
NetR83_1: R83.1 R85.2 R96.2 R97.2 U3.3 | length 388.2
  Top Layer w50: v1(2704.42,1128.52) R85.2@2704.42,1206.97
  Bottom Layer w8: v1(2704.42,1128.52) 2710.92,1128.52 2834.2,1005.24 2900.63,1005.24 2912.26,1016.86 2912.26,1035.86 2912.1,1036.01 U3.3@2912.1,1062.82
  other v1: 2706.33,1218.43
NetR84_1: R84.1 R98.2 R101.2 R102.2 U4.3 | length 476.6
  Top Layer w50: v1(2704.42,1459.16) 2705.34,1459.16 2705.34,1535.25 v1(2706.26,1535.25)
  Bottom Layer w8: v1(2706.26,1535.25) 2699.83,1535.25 2664.83,1570.25 2664.83,1644.39 2670.69,1650.25 2746,1650.25 2761.25,1635 2838,1635 2853,1650 2874.55,1650 2893.78,1630.77 2893.78,1627.62 2898.54,1622.86 U4.3@2898.54,1615.97
NetR86_2: R86.2 R87.2 R88.2 R90.2 U10.2 | length 145.2
  Bottom Layer w6: v1(1805.14,1038.95) 1805.73,1038.36 R86.2@1861.06,1038.36 1860.62,1037.92 R90.2@1860.62,993.67 R88.2@1860.62,949.51
NetR88_1: R88.1 U11.1 | length 631.3
  Int2(Signal) w6: v1(1905.9,950) 1938.17,982.27 1938.17,1098.17 2005.95,1165.95 2005.95,1342.8 v1(2101,1437.86)
  Bottom Layer w6: U11.1@2046.81,1417.57 2081,1417.57 2098,1434.57 v1@2098,1439
NetR91_1: R91.1 R92.1 U24.15 | length 432.4
  Top Layer w6: v1(2219,1750) 2219.86,1750 2234.88,1765.01 2260.58,1765.01 U24.15@2261.38,1765.81
  Int9(Signal) w6: v1(1992.4,1517.51) 1993.45,1518.56 2011.24,1518.56 2031.71,1539.03 2036.48,1539.03 2121,1623.55 2121,1727 2140,1746 2208.64,1746 2210.02,1747.38 2216.38,1747.38 v1(2219,1750)
NetR93_1: R93.1 R95.1 U24.11 | length 454.2
  Top Layer w6: v1(2219,1856.16) 2222.44,1856.16 2234.04,1844.55 U24.11@2261.38,1844.55
  Int9(Signal) w6: v1(1989.3,1567.68) 2109,1687.38 2109,1786 2179.16,1856.16 v1(2219,1856.16)
NetR94_2: R94.2 R99.2 U16.8 | length 77
  Top Layer w6: R99.2@1713,1824.38 1713,1820.44 1721.81,1811.63 1725.75,1811.63 1729.04,1808.33 U16.8@1776.33,1808.33 ; U16.8@1777,1808.33 U16.8@1781.67,1808.33
  other v1: 1716.79,1822.68
NetR103_1: R103.1 U18.1 U19.3 | length 598.4
  Top Layer w8: U19.3@1478.24,1204.02 v1(1525.48,1204.02) ; v1(1870.8,1439.32) 1873.03,1437.09 1873.03,1433.63 1889.1,1417.57 U18.1@1895,1417.57
  Int9(Signal) w8: v1(1525.48,1204.02) 1525.48,1241.1 1591.98,1307.61 1611.9,1307.61 1674.89,1370.6 1674.89,1390.52 1723.7,1439.32 v1(1870.8,1439.32)
  Bottom Layer w8: R103.1@1838.55,1457.51 1844.75,1451.3 1848.69,1451.3 1858.44,1441.56 1868.56,1441.56 v1(1870.8,1439.32)
NetR103_2: R103.2 U39.1 | length 592
  Int9(Signal) w6: v1(1845.83,1489.99) 1874.47,1461.35 1973.21,1461.35 1979.77,1467.91 2074.8,1467.91 2081.37,1461.35 2113.8,1461.35 2139.84,1487.39 v1(2139.84,1663.06)
  Bottom Layer w6: R103.2@1791.31,1457.51 1800.12,1466.32 1807.07,1466.32 1828.12,1487.37 1843.21,1487.37 v1(1845.83,1489.99) ; v1(2139.84,1663.06) 2149.84,1673.06 U39.1@2161.94,1673.06
NetR104_2: R104.2 U10.5
  other v1: 2031.78,938.36
NetR105_1: R105.1 R111.1 U10.6 U21.5 U21.8 U21.13 U21.16 | length 1126.3
  Int2(Signal) w6: v1(1852,874) 1852,694.38 1865.86,680.52 v1(1865.86,676.81)
  Int9(Signal) w6: v1(1852,874) 1905.72,927.72 1975.82,927.72 v1(2037.68,989.58) ; v1(1865.86,676.81) 1889.89,700.84 1999.1,700.84 2015.33,684.62 2015.33,664.84 v1(1996.48,646)
  Bottom Layer w6: v1(1865.86,676.81) 1865.86,677.12 1882.25,693.5 U21.8@1882.25,699.41 ; U21.13@1882.25,849.01 1882.25,854.92 1865.78,871.38 1854.62,871.38 v1(1852,874) 1896.15,918.15 2009.49,918.15 2013,914.63 2013,871.15 1986.85,845 1961.92,845 1959.02,847.91 U21.16@1959.02,849.01 ; U21.5@1959.02,699.41 1959.02,693.5 1977.64,674.88 1977.64,664.84 v1(1996.48,646)
  Bottom Layer w12: v1(2037.68,989.58) 2038.19,990.09 2038.19,1032.2 R111.1@2038.7,1032.71
NetR106_1: R106.1 U22.16 | length 104.5
  Top Layer w8: U22.16@1995.44,812.6 2001.34,812.6 2003.25,814.5 2003.25,843.01 2018.03,857.8 R106.1@2064.51,857.8
NetR107_2: R107.2 U21.1 | length 101
  Bottom Layer w8: U21.1@1995.44,812.6 1995.44,835.2 2018.03,857.8 R107.2@2064.51,857.8
NetR108_2: R108.2 U21.12 | length 104.9
  Bottom Layer w8: R108.2@1776.42,859 1780.51,863.08 1816.4,863.08 1838.96,840.53 1839.92,840.53 1845.83,834.62 U21.12@1845.83,812.6
NetR109_2: R109.2 U21.9 | length 77.3
  Bottom Layer w8: R109.2@1776.09,717.65 1821.75,717.65 1839.92,735.82 U21.9@1845.83,735.82
NetR111_2: R111.2 U22.1 U22.4 U22.9 U22.12 | length 883.9
  Top Layer w6: U22.9@1882.25,699.41 1879.34,696.5 1879.34,690.29 1879.19,690.14 1884.71,684.62 1884.71,659.33 v1(1883.79,658.42) ; U22.4@1882.25,849.01 1882.25,873.82 1876.2,879.87 1876.2,895.87 1895.26,914.93 1975.07,914.93 v1(1993,897) 1990.38,894.38 1990.38,886.28 1959.02,854.92 U22.1@1959.02,849.01 ; U22.12@1959.02,699.41 1973.89,699.41 v1(1996.48,676.81)
  Int2(Signal) w6: v1(1957.01,1032.71) 1957.01,984.9 1966.01,975.9 1966.01,917.83 1975.11,908.72 1978.08,908.72 1989.8,897 v1(1993,897) 1994.74,895.26 1994.74,678.55 v1(1996.48,676.81)
  Int9(Signal) w6: v1(1883.79,658.42) 1886.41,661.04 1886.41,674.75 1900.5,688.84 1981.87,688.84 1993.9,676.81 v1(1996.48,676.81)
  Bottom Layer w6: v1(1957.01,1032.71) R111.2@1991.46,1032.71
NetR112_1: R112.1 U21.4 | length 90
  Bottom Layer w8: U21.4@1995.44,735.82 1999.44,735.82 2001.34,733.92 2001.34,717.65 2010.72,708.28 R112.1@2064.51,708.28
NetR114_1: R114.1 R198.1 | length 1019.5
  Int2(Signal) w8: v1(2424.55,1367.89) 2424.55,1258.78 2389.59,1223.82 2389.59,919.24 2423.6,885.22 2423.6,556.14 2445.24,534.5 2565.77,534.5 v1(2585.62,554.34)
NetR114_2: R114.2 U25.10 U25.16 | length 427.9
  Top Layer w8: v1(2304.51,1404.78) 2323.39,1423.66 U25.10@2323.39,1455.01 ; U25.16@2410.99,1568.19 2411.39,1568.6 2449.6,1568.6 v1(2450,1569)
  Bottom Layer w8: v1(2304.51,1404.78) 2354.37,1454.64 2450,1454.64 ; v1(2424.55,1415.13) 2424.55,1419.07 2450,1444.52 2450,1454.64 ; v1(2450,1569) 2450,1454.64
NetR115_1: R115.1 R131.1 R182.1 U27.19 | length 2653.4
  Top Layer w8: v1(1047.21,989.58) 1047.21,992.74 1058.04,1003.57 U27.19@1058.04,1052.72
  Int4(Signal) w8: v1@633.74,1327.19 971.36,989.58 v1(1047.21,989.58)
  Int7(Signal) w6: v1(632.53,1326.88) 612.51,1306.85 500.85,1306.85 478,1284 478,741 605,614 1292.07,614 1332.61,573.46 1648.26,573.46 v1(1703.1,518.62)
NetR116_1: R116.1 R140.1 R184.1 U27.30 | length 2569.6
  Top Layer w10: U27.30@900.56,895.24 945.25,895.24 945.25,891.03 951.11,885.18 v1(951.11,882.56)
  Int4(Signal) w10: v1(633.74,1282.41) 633.74,1219.81 805.76,1047.8 805.76,1040.07 949.63,896.21 949.63,884.04 v1(951.11,882.56)
  Int7(Signal) w6: v1(633.74,1282.41) 606.18,1254.84 534.84,1254.84 498.16,1218.16 498.16,748.84 621,626 1297.28,626 1337.81,585.46 1682.95,585.46 v1(1749.79,518.62)
NetR117_1: R117.1 R139.1 R180.1 U27.18 | length 2782.7
  Top Layer w6: U27.18@1077.72,1052.72 1077.94,1052.94 1077.94,1110.92 v1(1078.16,1111.14)
  Int4(Signal) w8: v1(633.74,1372.55) 758.16,1372.55 893.92,1236.8 952.51,1236.8 v1(1078.16,1111.14)
  Int7(Signal) w6: v1(633.74,1372.55) 608.22,1347.03 482.03,1347.03 449,1314 449,728 575,602 1283,602 1328.79,556.21 1618.83,556.21 v1(1656.42,518.62)
  Bottom Layer w6: v1(1078.16,1111.14) 1097.41,1091.9 R117.1@1097.41,1036.82
NetR118_1: R118.1 R188.1 R221.2 U27.33 | length 1652
  Top Layer w8: U27.33@900.56,836.18 v1(949.77,836.18)
  Int5 (GND&PW) w8: v1(790,827.68) 793.16,827.68 804.5,816.34 865.63,816.34 885.47,836.18 v1(949.77,836.18)
  Int4(Signal) w8: v1(633.74,1094.06) 771,956.81 771,846.68 855,762.68 855,206.94 901.8,160.14 920.86,160.14 v1(923.1,157.9)
  Bottom Layer w8: v1(923.1,157.9) 958,123 1150.1,123 1218,190.9 R221.2@1218,216.38
NetR119_1: R119.1 U27.7 | length 63
  Top Layer w8: v1(1173.43,892.29) 1174.9,893.76 1233.73,893.76 U27.7@1235.2,895.24
NetR120_1: R120.1 R122.1 U30.5 | length 46
  Bottom Layer w12: R122.1@1670.04,716.43 R120.1@1670.04,762.47
  other v1: 1670.04,713.55
NetR121_1: R121.1 U30.6 U30.7 | length 1341.1
  Top Layer w10: v1(1584.95,860.79) 1602,860.79 1643.64,819.14 1643.64,818.75 1649.5,812.89 U30.7@1693.66,812.89 U30.6@1693.66,762.89
  Int2(Signal) w10: v1(1581.38,1569) 1563.14,1550.76 1563.14,1501.31 1578.63,1485.83 1578.63,1326.59 1557.25,1305.21 1557.25,1246.5 1557.79,1245.95 1557.79,1241.2 1584.95,1214.03 v1(1584.95,860.79)
  Int9(Signal) w10: v1(1216.19,1620.51) 1325.46,1620.51 1357.36,1588.61 1357.36,1558.08 1363.22,1552.22 1567.22,1552.22 1581.38,1566.38 v1(1581.38,1569)
NetR125_1: R125.1 U31.5 | length 96.5
  Top Layer w6: U31.5@1013.83,1516.56 1032.73,1516.56 1051.23,1535.07 v1(1051.23,1538.22)
  Bottom Layer w6: R125.1@1020.85,1502.49 1020.85,1506.43 1051.23,1536.81 v1(1051.23,1538.22)
NetR126_1: R126.1 R127.2 U31.3 | length 131.6
  Top Layer w8: U31.3@1013.83,1477.19 1069.32,1477.19 1072.77,1480.65 1072.77,1501.26 v1(1074,1502.49)
  Bottom Layer w8: R126.1@1074,1453.57 v1(1074,1502.49)
NetR128_2: R128.2 RN3.7 U32.3 U32.7 | length 1705
  Int2(Signal) w6: v1(1173.08,1540.19) 1175.7,1537.57 1175.7,1384.49 1187.64,1372.55 v1(1187.64,1368.84)
  Int9(Signal) w6: v1@1190,1370 1191.16,1368.84 1251.17,1368.84 1259.69,1377.36 1319.21,1377.36 1356.54,1340.04 1356.54,1224.75 1352.31,1220.53 1352.31,1143.69 1363.35,1132.65 1489.31,1132.65 1625.71,1269.05 1868.01,1269.05 1892.06,1245 v1(1950,1245)
  Bottom Layer w6: 1159,1440.52 1159,1416.53 1186.16,1389.37 v1@1186.16,1368.84 ; 1161.99,1440.52 1161.99,1441.18 1168.43,1447.61 1169.76,1447.61 1175.72,1453.57 U32.7@1182.81,1453.57 ; v1@1175.69,1537 1175.69,1539.09 1179.4,1542.8 1181.5,1542.8 1203.42,1564.72 1207.38,1564.72 R128.2@1216.19,1573.54 ; v1(1187.64,1368.84) 1223.84,1368.84 1232.36,1377.36 1319.74,1377.36 1339.35,1396.97 1339.35,1435.36 1307.42,1467.3 1306.09,1467.3 1300.13,1473.26 U32.3@1293.04,1473.26 ; RN3.7@1905.83,1246.17 1906.41,1245.58 1949.42,1245.58 v1(1950,1245)
NetR130_1: R130.1 U18.9 U19.5 | length 867.6
  Top Layer w10: U19.5@1690.83,1154.02 1697.65,1160.83 1734.43,1160.83 1745.42,1171.82 v1(1748.04,1171.82) ; U18.9@2044.61,1340.8 2100,1340.8 2103.38,1337.43 v1(2106,1337.43)
  Int9(Signal) w10: v1(1748.04,1171.82) 1772.13,1147.74 1906.83,1147.74 1909.33,1145.24 1926.6,1145.24 1929.09,1147.74 2026.64,1147.74 2086.22,1207.32 2086.22,1215.59 2098.43,1227.79 2100.14,1227.79 2106,1233.65 v1(2106,1337.43)
  Bottom Layer w10: R130.1@2076.36,1515.35 2076.36,1511.41 2083.17,1504.6 2111.07,1504.6 2126.84,1488.83 2126.84,1354.48 2111.64,1339.28 2107.85,1339.28 v1(2106,1337.43)
NetR130_2: R130.2 U39.2 | length 185.4
  Bottom Layer w10: R130.2@2076.36,1562.59 2129.84,1562.59 2181.63,1614.38 U39.2@2181.63,1673.06
NetR132_1: R132.1 U37.13 | length 92
  Top Layer w8: R132.1@1279.09,1796.35 1286.9,1804.16 1294.5,1804.16 1295.52,1805.18 U37.13@1367.46,1805.18
NetR133_2: R133.2 U36.6 | length 141.4
  Top Layer w8: U36.6@1001.76,1832.85 1029.41,1832.85 1040.75,1844.19 1074.71,1844.19 1086.04,1832.85 1113.8,1832.85 1125.13,1844.19 R133.2@1129.07,1844.19
NetR134_1: R134.1 R177.1 R215.1 U36.10 | length 3524.7
  Top Layer w8: v1(633.62,1880) 755.14,1880 802.69,1927.55 912.46,1927.55 R134.1@933.74,1906.27 ; U36.10@917.11,1848.6 917.11,1873.7 930.03,1886.62 930.03,1902.56 R134.1@933.21,1905.74
  Int4(Signal) w6: v1(974,367) 1395.27,367 1516.37,488.1 v1(1516.37,518.62)
  Int7(Signal) w6: v1(633.62,1880) 613.67,1880 594.82,1898.84 553.84,1898.84 535.84,1880.84 535.84,1857.11 524.8,1846.08 501.07,1846.08 212.76,1557.76 212.76,495.24 399.5,308.5 871.5,308.5 930,367 v1(974,367)
NetR134_2: R134.2 R135.1 R183.1 R216.1 U36.11 | length 3317.8
  Top Layer w8: v1(633.62,1789.25) R135.1@633.62,1835.3 730.98,1835.3 801.42,1905.74 890.97,1905.74 890.97,1881.37 897.43,1874.9 U36.11@897.43,1848.6
  Int7(Signal) w6: v1(633.62,1789.25) 631.39,1791.48 612.2,1791.48 594.6,1809.09 515.47,1809.09 233,1526.62 233,563 290,506 1000.35,506 1010.2,515.84 1025.8,515.84 1036.65,505 1150.41,505 1172.41,483 1377.25,483 1384.47,490.22 1586.8,490.22 1605.15,508.56 1605.15,510.33 1609.74,514.92 v1(1609.74,518.62)
NetR136_1: R136.1 U37.12 | length 119.5
  Top Layer w8: R136.1@1279.09,1844.19 1328.37,1844.19 1341.79,1830.77 U37.12@1393.05,1830.77
NetR137_2: R137.2 U36.5 | length 149.4
  Top Layer w6: U36.5@1001.76,1813.17 1008.65,1813.17 1010.57,1815.09 1010.57,1815.42 1014.09,1818.93 1033.88,1818.93 1037.62,1822.68 1045.2,1822.68 1053.72,1831.19 1069.32,1831.19 1104.16,1796.35 R137.2@1129.07,1796.35
NetR143_1: R143.1 U37.19 | length 131.6
  Top Layer w8: R143.1@1279.09,1702.73 1282.93,1702.73 1290.74,1694.92 1290.74,1685.85 1295.43,1681.17 1322.67,1681.17 1326.76,1685.26 1343.2,1685.26 1347.3,1681.17 U37.19@1393.05,1681.17
NetR144_2: R144.2 U36.2 | length 147.9
  Top Layer w6: U36.2@1001.76,1754.11 1019.08,1754.11 1046.75,1726.44 1093.25,1726.44 1108.07,1741.27 1121.78,1741.27 R144.2@1129.07,1748.55
NetR145_1: R145.1 U37.18 | length 108
  Top Layer w8: R145.1@1279.09,1748.55 1283.03,1748.55 1290.84,1740.74 1290.84,1736.81 1320.88,1706.76 U37.18@1367.46,1706.76
NetR146_2: R146.2 U36.1 | length 146.8
  Top Layer w6: U36.1@1001.76,1734.43 1001.76,1723.5 1022.53,1702.73 R146.2@1129.07,1702.73
NetR147_1: R147.1 R150.1 U40.2 | length 121.8
  Top Layer w8: R150.1@1320.51,2113.85 R147.1@1369.55,2113.85 1368.96,2114.44 1368.96,2185.57 U40.2@1368.37,2186.16
NetR148_1: R148.1 R152.1 U40.25 | length 139.7
  Top Layer w8: R152.1@1241.87,2202.71 1245.81,2202.71 1279.46,2236.36 U40.25@1326.05,2236.36
  Top Layer w20: R148.1@1241.68,2161.18 1241.87,2161.38 R152.1@1241.87,2202.71
NetR149_2: R149.2 U41.23 | length 72.3
  Top Layer w10: U41.23@1964.69,2182.22 1964.69,2134.51 1979.32,2119.88 R149.2@1979.32,2115.94
NetR151_1: R151.1 R153.1 U41.22 | length 72.1
  Top Layer w10: v1(1931.06,2115.94) 1931.06,2119.88 1945.01,2133.83 U41.22@1945.01,2182.22
NetR154_2: R154.2 U40.1 | length 117.9
  Top Layer w8: R154.2@1241.68,2116.69 1249.49,2124.5 1267.38,2124.5 1328.61,2185.73 U40.1@1330.97,2185.73
NetR155_2: R155.2 R156.1 U43.5 | length 80.1
  Top Layer w10: U43.5@2299.19,2112.66 2299.19,2055.4 2312.56,2042.03 v1(2316.5,2042.03)
NetR157_1: R157.1 R159.1 U42.2 | length 128.5
  Top Layer w8: R159.1@792.12,2493.86 R157.1@792.12,2448.03 856.45,2448.03 861.1,2452.68 U42.2@872.91,2452.68
NetR158_1: R158.1 R160.1 U42.25 | length 277.2
  Top Layer w8: R158.1@738.5,2611.38 R160.1@791.4,2611.38 791.4,2583.82 796.09,2579.14 887.16,2579.14 923.1,2543.19 U42.25@923.1,2495
NetR162_2: R162.2 U42.1 | length 123.8
  Top Layer w8: R162.2@792.12,2541.89 858.14,2541.89 872.47,2527.56 U42.1@872.47,2490.08
NetR163_2: R163.2 U38.3 U38.4 | length 1438.2
  Int2(Signal) w10: v1(633.62,2389.56) 735.08,2288.1 v1(735.08,1690.09)
  Int9(Signal) w10: v1(735.08,1690.09) 1048.7,1690.09 1057.62,1681.17 1319.24,1681.17 v1(1334.98,1665.42)
  Bottom Layer w10: U38.3@1334.98,1630.97 v1(1334.98,1665.42) U38.4@1334.98,1717.59
NetR165_2: R165.2 U12.2 | length 2085.6
  Int2(Signal) w8: v1(633.62,2298.37) 668.31,2298.37 714,2252.68 714,1218.05 v1(861.05,1071)
  Int9(Signal) w8: v1(861.05,1071) 1106.15,1071 1110.54,1066.6 1385.6,1066.6 1419.14,1100.14 v1(1543.66,1100.14)
  Bottom Layer w8: U12.2@1498.39,1100.32 1498.47,1100.23 1543.57,1100.23 v1(1543.66,1100.14)
NetR166_2: R166.2 U12.8 | length 2333.5
  Int2(Signal) w8: v1(633.62,2256.81) 672.21,2256.81 700,2229.02 700,1212.25 826.6,1085.65 v1(826.6,1048.71)
  Int9(Signal) w8: v1(826.6,1048.71) 1187.62,1048.71 1230.03,1006.3 1588.36,1006.3 1702.06,1120 v1(1728.2,1120)
  Bottom Layer w8: U12.8@1671.61,1120 v1(1728.2,1120)
NetR167_2: R167.2 U35.3 U35.4 | length 1153.5
  Int2(Signal) w8: v1(633.74,2214.24) 679.62,2168.36 v1(679.62,1937)
  Int9(Signal) w8: 744,1942.17 684.79,1942.17 v1(679.62,1937) v1(1331.26,1937)
  Bottom Layer w8: v1(1331.26,1937) 1331.26,1933.84 1336.87,1928.23 U35.4@1336.87,1886.88 U35.3@1336.87,1800.26
NetR169_1: R169.1 R192.1 | length 2790.5
  Int7(Signal) w8: v1(633.62,2066.73) 613.78,2046.89 613.78,2018.21 629.14,2002.84 725.66,2002.84 812.5,1916 881.37,1916 1068.61,1728.75 1308.79,1488.58 1308.79,1441.21 1325.38,1424.62 1343.3,1424.62 1391.46,1376.46 1397.22,1376.46 1427.9,1345.78 1427.9,1345.4 1588.3,1185 1700,1185 1739.07,1145.93 1833.72,1145.93 1937.17,1042.49 1937.17,1024.5 1964.69,996.97 1964.69,975.81 2110.14,830.35 2129.65,830.35 2304.88,655.12 2512.9,655.12 2526.9,641.12 2603.53,641.12 v1(2690.3,554.34)
NetR170_2: R170.2 R222.1 U36.16 | length 2342.4
  Top Layer w6: v1(633.62,1576) 664.6,1576 842.71,1754.11 U36.16@871.84,1754.11
  Int7(Signal) w6: v1(633.62,1576) 613.03,1576 588.87,1551.84 499.84,1551.84 391,1443 391,759 560,590 1278,590 1324.35,543.65 1324.35,521.24 v1(1326.96,518.62)
NetR171_1: R171.1 R191.1 | length 2765.4
  Int7(Signal) w8: v1(633.62,2026.43) 635.2,2028 725,2028 823,1930 887.16,1930 1024.66,1792.5 1061.88,1792.5 1135.27,1719.11 1135.27,1713.75 1171.96,1677.05 1291.65,1677.05 1360.75,1607.96 1360.75,1565.66 1415.71,1510.69 1456.19,1510.69 1605,1361.88 1655.56,1361.88 1772.24,1245.2 1771.46,1244.43 1771.46,1227.99 1876.83,1122.62 1895.16,1122.62 2000.53,1017.26 2000.53,1000.47 2017.83,983.17 2017.83,981.36 2029.46,969.73 2031.27,969.73 2306.2,694.8 2493.02,694.8 2532.7,655.12 2617.59,655.12 2716.13,556.58 2735.69,556.58 v1(2737.93,554.34)
NetR172_2: R172.2 R223.1 U36.15 | length 2370.4
  Top Layer w6: v1(633.62,1616.59) 637.04,1620 691.63,1620 837.74,1766.11 838.32,1766.11 846,1773.8 U36.15@871.84,1773.8
  Int7(Signal) w6: v1(633.62,1616.59) 613.03,1616.59 591.28,1594.84 496.02,1594.84 372,1470.82 372,746 544,574 1255.76,574 1279.64,550.12 v1(1279.64,518.62)
NetR174_2: R174.2 R224.1 U36.14 | length 2404.6
  Top Layer w6: v1(633.62,1664.02) 667.9,1664.02 795.44,1791.56 839.38,1791.56 841.3,1793.48 U36.14@871.84,1793.48
  Int7(Signal) w6: v1(633.62,1664.02) 613.03,1664.02 584.44,1635.43 476.37,1635.43 350.5,1509.55 350.5,729.5 522,558 1220.92,558 1232.32,546.6 v1(1232.32,518.62)
NetR178_1: R178.1 R214.1 U36.12 | length 2987.2
  Top Layer w6: v1(633.62,1745.44) 693.64,1745.44 789.45,1841.24 836.72,1841.24 845.11,1832.85 U36.12@871.84,1832.85
  Int7(Signal) w6: v1(633.62,1745.44) 613.67,1745.44 594.82,1764.28 529.34,1764.28 267,1501.94 267,673 412,528 1148.97,528 1177.2,499.78 1377.06,499.78 1414.74,537.46 1548.54,537.46 1557.89,528.11 1557.89,527.49 1563.05,522.33 v1(1563.05,518.62)
NetR179_1: R179.1 R225.1 U36.13 | length 2498.2
  Top Layer w6: v1(633.62,1705) 687.4,1705 785.95,1803.56 834.41,1803.56 844.02,1813.17 U36.13@871.84,1813.17
  Int7(Signal) w6: v1(633.62,1705) 613.02,1705 590.88,1682.86 479.99,1682.86 293.04,1495.91 293.04,671.96 419,546 1172.33,546 1185,533.33 v1(1185,518.62)
NetR181_1: R181.1 R217.1 U36.17 | length 367.7
  Top Layer w6: R217.1@633.62,1487 v1(633.62,1533) 663.52,1533 864.95,1734.43 U36.17@871.84,1734.43
NetR185_1: R185.1 R219.2 U27.32 | length 1361.1
  Top Layer w10: v1(806,864) 824.34,864 832.47,855.87 U27.32@900.56,855.87
  Int4(Signal) w10: v1(633.62,1142.28) 790,985.9 790,880 v1(806,864) 834.45,864 874,824.45 874,264.38 v1@922.94,215.44
  Bottom Layer w10: v1(923,215.38) 1121.4,215.38 R219.2@1122.4,216.38
NetR186_1: R186.1 R220.2 U27.34 | length 1648
  Top Layer w10: v1(790,794) 833.5,794 856,816.5 U27.34@900.56,816.5
  Int4(Signal) w10: v1(633.74,1048.71) 753,929.45 753,831 v1(790,794) 840,744 840,200.73 895.59,145.14 896.24,145.14 909.38,132 v1(912,132)
  Bottom Layer w10: v1(912,132) 939,105 1205.16,105 1255.28,155.12 1255.28,230.96 1283,258.68 R220.2@1283,262.62
NetR187_1: R187.1 R218.2 U27.31 | length 1539.4
  Top Layer w10: v1(820.32,890.64) 835.41,875.55 U27.31@900.56,875.55
  Int4(Signal) w10: v1(633.74,1190.34) 727.03,1097.05 727.03,1089.11 819.16,996.99 819.16,891.81 841.19,891.81 900.76,832.24 900.76,286.13 943.84,243.05 943.84,206.74 918.95,181.85 911.85,181.85 v1(910,180)
  Bottom Layer w10: v1(910,180) 911.7,180 920.7,189 1156.67,189 1162.53,194.86 1162.53,209.57 R218.2@1169.34,216.38
NetR197_2: R197.2 U26.13 | length 885.4
  Top Layer w8: U26.13@2404.51,964.34 2432.71,964.34 v1(2458.3,938.75)
  Bottom Layer w8: v1(2458.3,938.75) 2503.1,893.95 2503.1,670.37 2606.76,566.7 R197.2@2606.76,179.27
NetR199_2: R199.2 U26.14 | length 926.4
  Top Layer w8: U26.14@2404.51,984.03 2447.83,984.03 2455.14,976.72 v1(2458.3,976.72)
  Bottom Layer w8: v1(2458.3,976.72) 2423.6,942.02 2423.6,624.1 2477.35,570.36 2477.35,443.76 2563.11,358 R199.2@2563.11,179.27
